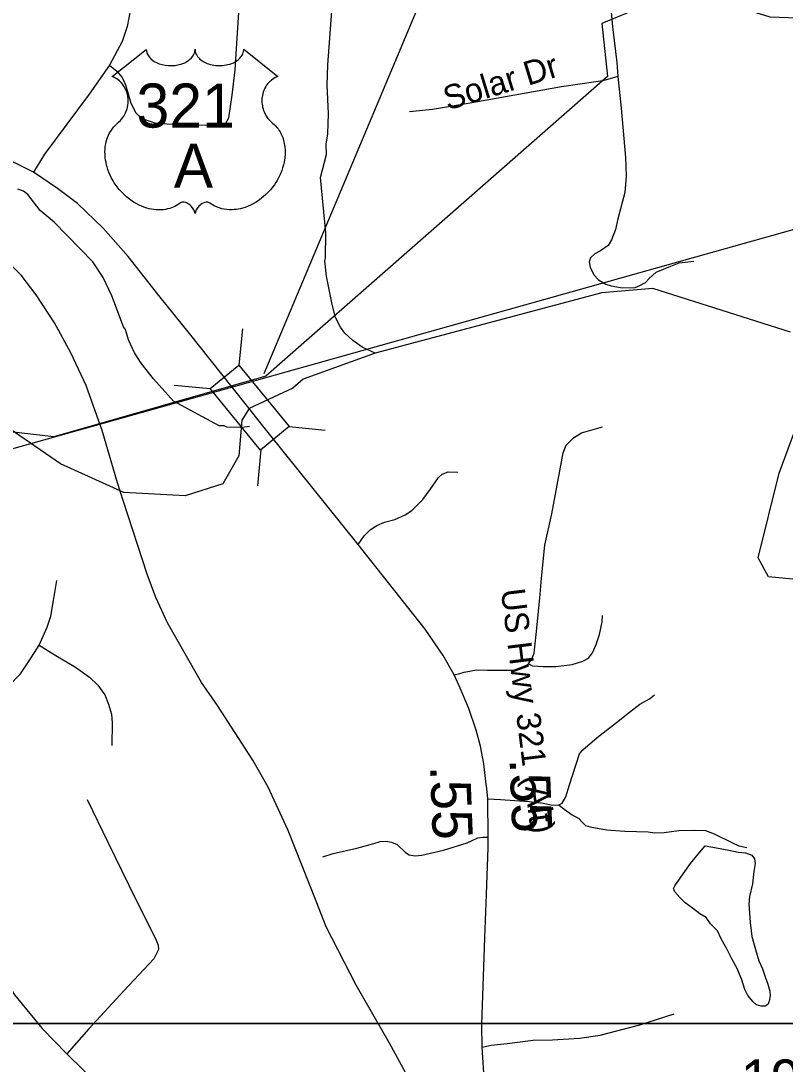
# Model space of a CAD drawing. Extents: x 1159738 to 1321356, y 736314 to 882035.
# Drawn here: x 1263980 to 1266364, y 766631 to 769885 of the extents above; entities that cross this region are included whole.
import ezdxf

# ---------------------------------------------------------------- set-up
doc = ezdxf.new("R2010")
doc.units = 0
for name, color, linetype in [('Exist Boundary Political City Limit New', 7, 'Continuous'), ('Exist Hydrographic Creek Single Shore', 7, 'Continuous'), ('Exist Hydrographic Misc Water Feature', 7, 'Continuous'), ('Exist Railroad Mainline', 7, 'Continuous'), ('Exist Road Non-System Type 51', 7, 'Continuous'), ('Exist Road Non-System Type 51 Label', 7, 'Continuous'), ('Exist Road Primary US Attributed', 7, 'Continuous'), ('Exist Road Primary US Label', 7, 'Continuous'), ('Exist Road Primary US Mileage Hundredths English Label', 7, 'Continuous'), ('Exist Road Primary US Shield CELL', 7, 'Continuous'), ('Exist Road Primary US Shield Number Label', 7, 'Continuous'), ('Exist Road Primary US Structure Standard Bridge CELL', 7, 'Continuous'), ('Exist Road Primary US Structure Standard Bridge Number Label', 7, 'Continuous'), ('Exist Road Secondary Mileage Hundredths English Label', 7, 'Continuous'), ('Exist Road Secondary Type 51 Number Label', 7, 'Continuous'), ('Map Preparation Boundary City Limit Buffer Line', 7, 'Continuous'), ('Map Preparation Inset Cut Line', 7, 'Continuous')]:
    doc.layers.add(name, color=color, linetype=linetype)

msp = doc.modelspace()

# ---------------------------------------------------------------- linework, layer by layer
at = {"layer": 'Exist Boundary Political City Limit New'}
for points in [[(1269986.4, 767284.9), (1268765.1, 767350.1), (1268594.9, 767532.3), (1268556.9, 767615.5), (1268556.9, 767674.9), (1268622, 767726), (1268786.7, 767711.3), (1268877.3, 767705.2), (1268933.1, 767837.1), (1268535.6, 768192.7), (1268644.9, 768487.5), (1268350.3, 768435.6), (1268332.7, 768458.1), (1268702.9, 769072.4), (1268291.5, 769323.6), (1267446.1, 769337.6), (1267449.1, 769737.8), (1267001.2, 769871.7), (1266318, 769896.5), (1266044.5, 769981.8), (1265792.3, 769877.3)], [(1265792.3, 769877.3), (1265809.7, 769711.8), (1264744.6, 768776.5), (1264082.9, 768587.5), (1263937.9, 768604.2), (1263679, 768704), (1263519.8, 768756.3), (1263427.7, 768754), (1263283.6, 768762.9), (1263035.1, 768711.1), (1262987.6, 768666), (1262932.9, 768525.7), (1262858.7, 768534.6), (1262700.3, 768541.9), (1262545.5, 768495), (1262098, 769128.8), (1262093.3, 768800.7), (1261203.3, 768836.2), (1261208, 768957.4), (1261046.5, 768957.4), (1261049.7, 769475.1), (1259666.9, 769484.6)], [(1260127.9, 766946.1), (1260871.4, 766933.2), (1261094.9, 766804.1), (1261119.5, 767044.5), (1261149.6, 767207.9), (1261209.7, 767384.2), (1261291.4, 767509), (1261424.1, 767761.8), (1261514.3, 767705.8), (1261634.7, 767718.7), (1261798, 767783.3), (1261991.4, 767925.2), (1262133.3, 768084.3), (1262546.9, 768155.9), (1267067, 769424.4), (1268424.7, 767365), (1269986.4, 767284.9)]]:
    msp.add_lwpolyline(points, dxfattribs=at)
at = {"layer": 'Exist Hydrographic Creek Single Shore'}
for points in [[(1266381.5, 768913.8), (1265951.5, 769050.5), (1265792.5, 769037.3), (1265085.8, 768848.9), (1264860.4, 768767.1), (1264828.4, 768739), (1264692.7, 768676.2)], [(1264692.7, 768676.2), (1264669.5, 768639.1), (1264660.4, 768528.3), (1264610.4, 768440.6), (1264492.4, 768403.6), (1264301.4, 768414), (1264103.4, 768503.3), (1263725.4, 768763.6), (1263543.4, 768826.3), (1263368.4, 768823.3), (1263125.4, 768746.2), (1263023.4, 768672.7), (1262854.5, 768242.8), (1262679.4, 768031.4), (1262372.4, 767970.2), (1262106.6, 768081.9), (1261784.4, 768477.6), (1261579.5, 768632.8), (1261488.4, 768660.8), (1261030.4, 768686.4), (1260890.4, 768741.7), (1260734.4, 768853.2)], [(1266453.4, 768137.7), (1266312.5, 768150.4), (1266280.5, 768210.1), (1266345.5, 768474.7), (1266443.5, 768738.6)]]:
    msp.add_lwpolyline(points, dxfattribs=at)
at = {"layer": 'Exist Hydrographic Misc Water Feature'}
for points in [[(1265085.8, 768848.9), (1265045.1, 768867.4), (1265015.7, 768888.3), (1264990.3, 768911), (1264976.9, 768929.4), (1264961.7, 768959.8), (1264950.8, 769000.1), (1264933.2, 769088.6), (1264928.6, 769136.7), (1264930.8, 769144.7), (1264931, 769224.6), (1264914.3, 769397.1), (1264933.8, 769468.5), (1264932.7, 769500.5), (1264937.5, 769532.4), (1264939.3, 769596.3), (1264935.7, 769684.4), (1264937.5, 769748.3), (1264950.2, 769915.9)], [(1264692.9, 768619.4), (1264670.1, 768616.3), (1264622.1, 768617.6), (1264614.2, 768621.8), (1264598.2, 768622.3), (1264456.3, 768698.4), (1264394.2, 768768.1), (1264355.6, 768817.2), (1264334.4, 768849.8), (1264315.6, 768890.4), (1264306.4, 768922.6), (1264300.7, 768930.8), (1264263.4, 769027.8), (1264236.9, 769084.5), (1264204.8, 769133.8), (1264083.7, 769256.9), (1264040.7, 769294.2), (1264002, 769343.2), (1263988.4, 769353.6), (1263970.6, 769360.1)], [(1266020.2, 767186.5), (1266046.1, 767223.8), (1266069.2, 767257), (1266092.9, 767285.8), (1266115, 767311.8), (1266150, 767305.1), (1266188.5, 767298.4), (1266217.8, 767291.9), (1266240.7, 767289.9), (1266260.6, 767283), (1266269, 767271.3), (1266270.7, 767256.1), (1266266.5, 767231.2), (1266262, 767192.6), (1266253.1, 767153.4), (1266251.2, 767129.7), (1266252.6, 767102.5), (1266254.7, 767072.3), (1266260.9, 767029.1), (1266272.1, 766988.7), (1266282.7, 766953.3), (1266293.5, 766927.9), (1266301.6, 766903.3), (1266310.3, 766880.1), (1266317, 766858.5), (1266317.3, 766843.4), (1266314, 766827), (1266310.2, 766816.4), (1266302.2, 766811.5), (1266290, 766811.8), (1266275, 766815.1), (1266264.5, 766825.4), (1266247.8, 766844.5), (1266238.9, 766863.3), (1266228.9, 766893.7), (1266214.7, 766929.2), (1266198.2, 766959), (1266183.1, 766988.1), (1266165.2, 767021.5), (1266152.9, 767046.2), (1266131.3, 767068.3), (1266118.2, 767088), (1266098.3, 767099.2), (1266075.8, 767117), (1266052.6, 767134.1), (1266036.4, 767148.9), (1266020.4, 767168.6), (1266015.7, 767178.7), (1266020.2, 767186.5)]]:
    msp.add_lwpolyline(points, dxfattribs=at)
at = {"layer": 'Exist Railroad Mainline'}
for points in [[(1264281.3, 768444.1), (1264233.5, 768607.8), (1264183.6, 768747.6), (1264136.4, 768849.8), (1264085.4, 768942.9), (1264028.3, 769030.3), (1263981, 769091.8), (1263927.3, 769146.5), (1263875.7, 769189.9), (1263816.4, 769230.6), (1263736.9, 769273.8), (1263650.2, 769312.2), (1263545.8, 769354), (1263471.5, 769380.8), (1263402.3, 769405.5), (1263335.3, 769424.2), (1263249, 769444), (1263167.5, 769457), (1263075.7, 769468.5), (1263015.5, 769476.9)], [(1265522.8, 765944.2), (1265401.8, 766180.2), (1265353.4, 766273.7), (1265211.8, 766545.2), (1265130.2, 766695.9), (1265026.4, 766877.3), (1264932.6, 767059.2), (1264900.8, 767138.9), (1264813.5, 767359.9), (1264751.5, 767494.9), (1264703.2, 767579), (1264593.4, 767749), (1264544, 767821), (1264437.1, 768007.3), (1264400.9, 768086.5), (1264374.5, 768159), (1264299.9, 768385.6), (1264281.3, 768444.1)]]:
    msp.add_lwpolyline(points, dxfattribs=at)
at = {"layer": 'Exist Road Non-System Type 51'}
for points in [[(1266066, 770870.2), (1266030.6, 770807.6), (1265948.3, 770665.5), (1265942.1, 770652.5), (1265918.2, 770591.5), (1265896.9, 770544.9), (1265847.6, 770463.9), (1265831.8, 770434.7), (1265818.1, 770399.7), (1265807.8, 770366.1), (1265798.9, 770317.4), (1265794.1, 770271.4), (1265790.1, 770205.1), (1265793.5, 770140), (1265800.3, 770069.1), (1265817.5, 769957.9), (1265825.5, 769867.2), (1265839.4, 769755.3), (1265842.1, 769712)], [(1264356.4, 770405.7), (1264340.8, 770174.4), (1264325.3, 769971.9), (1264322.5, 769922), (1264311.7, 769867.8), (1264295.6, 769821.1), (1264256.8, 769746.9), (1264193.6, 769657), (1264053.8, 769469.2), (1264019, 769413.7)], [(1264256.8, 769746.9), (1264279.2, 769728.6), (1264296, 769708.2), (1264306.2, 769685.5), (1264323, 769628.6), (1264339, 769598.7), (1264357.9, 769581.2), (1264404.6, 769565.2), (1264593.4, 769559.4), (1264619.6, 769565.9), (1264628.4, 769582.7), (1264639.3, 769653.4), (1264648.8, 769732.2), (1264654.6, 769831.4), (1264663.4, 769961.4)], [(1265842.1, 769712), (1265795.2, 769698.7), (1265666.4, 769679.5), (1265375.5, 769627.4), (1265263.7, 769608.7), (1265192.5, 769601.8)], [(1265842.1, 769712), (1265853.2, 769613.3), (1265866, 769459.3), (1265868.1, 769401.2), (1265863.8, 769349.5), (1265842, 769268.2), (1265834.6, 769234.7), (1265822.9, 769202.7), (1265812.7, 769185), (1265788.8, 769167.4), (1265770.7, 769158.4), (1265756.8, 769146.1), (1265752.6, 769133.3), (1265755.8, 769116.8), (1265768, 769093.4), (1265782.4, 769077.9), (1265805.3, 769064.1), (1265821.8, 769058.7), (1265856.9, 769052.3), (1265896.8, 769053.9), (1265911.2, 769059.3), (1265928.8, 769069.4), (1265940.5, 769081.6), (1265961.8, 769101.4), (1266008.1, 769120.5), (1266033.6, 769130.7), (1266079.4, 769135.5)], [(1265563.2, 767879.9), (1265574.5, 767894.8), (1265580.9, 767912.5), (1265587.2, 767971.3), (1265598.6, 768084.6), (1265604.2, 768146.2), (1265614.8, 768249.9), (1265636, 768346.9), (1265661.4, 768481.1), (1265672, 768537.7), (1265681.2, 768561.1), (1265703.9, 768584.5), (1265729.3, 768600.1), (1265794.4, 768619.2)], [(1265032.2, 768251.7), (1265051.3, 768278.6), (1265069.7, 768297.7), (1265091, 768311.2), (1265114.3, 768321.8), (1265146.2, 768329.6), (1265179.4, 768344.5), (1265199.9, 768357.9), (1265233.9, 768391.9), (1265256.6, 768423.1), (1265282.7, 768460.6), (1265294.6, 768471.1), (1265313, 768478.2), (1265343.4, 768477.5)], [(1264037.5, 767937.8), (1264061.7, 767993.7), (1264073.5, 768028.3), (1264082.2, 768076.6), (1264092.5, 768139.2)], [(1265563.2, 767879.9), (1265576.3, 767872.8), (1265609.6, 767870.6), (1265648.5, 767871.3), (1265699.5, 767877.7), (1265732.7, 767887.6), (1265751.1, 767896.8), (1265763.2, 767913.8), (1265774.5, 767939.3), (1265785.1, 767971.2), (1265793.6, 768010.1), (1265795, 768030)], [(1263912.4, 767779.5), (1263935.2, 767803.1), (1263978.6, 767848.7), (1264005.8, 767888.4), (1264037.5, 767937.8)], [(1264037.5, 767937.8), (1264084.4, 767908.3), (1264150.6, 767868.6), (1264193.9, 767837.7), (1264220.4, 767812.7), (1264241.8, 767782.5), (1264253.5, 767753.8), (1264262.3, 767722.9), (1264264.5, 767695.6), (1264263.8, 767625.1)], [(1265332, 767845.3), (1265349.7, 767849.6), (1265362.9, 767853), (1265401.8, 767860.8), (1265435.8, 767860.1), (1265520, 767860.1), (1265540.5, 767865), (1265557.5, 767875), (1265563.2, 767879.9)], [(1265657.8, 767439.5), (1265668.4, 767444.5), (1265680.4, 767464.3), (1265691.1, 767501.9), (1265722.9, 767598.9), (1265733.5, 767611.6), (1265778.1, 767649.9), (1265838, 767696), (1265878.4, 767728.6), (1265910.9, 767753.4), (1265941.3, 767769.7), (1265956.9, 767783.2)], [(1264187.2, 767456.2), (1264252.1, 767320.8), (1264337.6, 767146.4), (1264400.4, 767023), (1264408, 767001.3), (1264409.1, 766988.3), (1264404.7, 766977.5), (1264395, 766959.1), (1264300.9, 766859.1), (1264191.6, 766741), (1264123.1, 766662.3)], [(1265437, 767457.9), (1265475.9, 767455.8), (1265565.8, 767450.2), (1265609, 767444.5), (1265634.4, 767439.5), (1265648.6, 767438.1), (1265657.8, 767439.5)], [(1265657.8, 767439.5), (1265674.8, 767425.6), (1265700.2, 767408.6), (1265720.8, 767396.6), (1265730.7, 767385.2), (1265741.1, 767375.4), (1265756, 767370.5), (1265806.9, 767362), (1265864.3, 767357.7), (1265937.2, 767355.6), (1265957, 767352), (1265986.7, 767353.5), (1266032.7, 767359.1), (1266082.2, 767360.5), (1266116.2, 767359.1), (1266142.4, 767349.2), (1266200.4, 767320.9), (1266220, 767311.7), (1266244.8, 767306.1)], [(1264922.3, 767276.8), (1264954.1, 767288.1), (1265027.7, 767304.4), (1265081.5, 767319.3), (1265101.3, 767325), (1265118.3, 767325.7), (1265136, 767323.5), (1265154.4, 767315.7), (1265179.9, 767290.3), (1265191.2, 767283.2), (1265210.3, 767280.3), (1265230.8, 767282.5), (1265298.8, 767298), (1265372.4, 767321.4), (1265405.6, 767337), (1265421.2, 767339.1), (1265438.2, 767339.1)], [(1263918.2, 766911.8), (1263960.2, 766847.2), (1264046.1, 766741.8), (1264123.1, 766662.3)], [(1265418.9, 766683), (1265447.2, 766690), (1265497.4, 766695), (1265578.1, 766704.9), (1265638.9, 766706.3), (1265723.2, 766712), (1265786.9, 766720.5), (1265911, 766753), (1265989.5, 766778.5), (1266018.4, 766787.9)], [(1264123.1, 766662.3), (1264282, 766507.8), (1264434.9, 766363.3), (1264579.5, 766228.5), (1264692.8, 766118.8), (1264845.4, 765980.1), (1264897.2, 765926.5), (1264922.8, 765887.5), (1264941.6, 765846.3), (1264960.4, 765784.4)]]:
    msp.add_lwpolyline(points, dxfattribs=at)
at = {"layer": 'Exist Road Primary US Attributed'}
for points in [[(1264638.8, 768742.9), (1264506.2, 768909.8), (1264414.9, 769023.8), (1264314.5, 769150.6), (1264236.8, 769238.1), (1264156.8, 769315.3), (1264094.5, 769362.7), (1264019, 769413.7), (1263903.1, 769470.6)], [(1264692.7, 768676.2), (1264638.8, 768742.9)], [(1265426.4, 766571.3), (1265418.9, 766683), (1265418.5, 766754), (1265427.4, 767025), (1265432.2, 767159.4), (1265437.6, 767306.2), (1265438.2, 767339.1), (1265437, 767457.9), (1265433.6, 767490.6), (1265432.1, 767503.6), (1265424.2, 767567.1), (1265413.8, 767622.3), (1265400.5, 767672.7), (1265377.8, 767739.7), (1265347.8, 767811.2), (1265332, 767845.3), (1265297.1, 767905.1), (1265241.5, 767987.7), (1265032.2, 768251.7), (1264755.7, 768595.5), (1264735.2, 768621.7), (1264692.7, 768676.2)]]:
    msp.add_lwpolyline(points, dxfattribs=at)
at = {"layer": 'Exist Road Primary US Shield CELL'}
msp.add_lwpolyline([(1264371.3, 769796.5), (1264371.6, 769792.1), (1264372.7, 769786.9), (1264373.5, 769784.2), (1264375.9, 769779), (1264380, 769773), (1264385.6, 769767), (1264391.9, 769761.8), (1264396.2, 769759), (1264403.4, 769755.1), (1264411.7, 769751.7), (1264420.8, 769749), (1264430.2, 769747.1), (1264440.4, 769746), (1264450.5, 769745.8), (1264461.4, 769746.6), (1264473.5, 769749), (1264479.1, 769750.4), (1264485.3, 769752.5), (1264491.1, 769754.9), (1264497.4, 769758.3), (1264502.5, 769761.6), (1264506.5, 769764.5), (1264512.1, 769769.9), (1264516.6, 769775.5), (1264518.5, 769778.6), (1264520.1, 769781.6), (1264522.4, 769788), (1264523, 769790.9), (1264523.4, 769796.7), (1264523.8, 769791.8), (1264524.3, 769788.7), (1264525.1, 769785.7), (1264526.4, 769782.5), (1264528.6, 769778), (1264531.1, 769774.2), (1264535.9, 769768.6), (1264538.8, 769765.9), (1264541.5, 769763.7), (1264548.7, 769758.7), (1264557.2, 769754.4), (1264561.3, 769752.6), (1264565.6, 769751.1), (1264571, 769749.5), (1264576.6, 769748.1), (1264582.1, 769747.2), (1264587.8, 769746.4), (1264593.5, 769746), (1264598.2, 769745.8), (1264604, 769745.9), (1264609.3, 769746.2), (1264614.8, 769746.8), (1264620.8, 769747.8), (1264625.7, 769748.9), (1264632.1, 769750.6), (1264637.8, 769752.7), (1264642.9, 769754.9), (1264649.5, 769758.3), (1264654.9, 769761.7), (1264658.7, 769764.8), (1264663.4, 769769.1), (1264667.8, 769774.1), (1264670.4, 769777.9), (1264672.2, 769781.7), (1264673.9, 769785.7), (1264674.9, 769790), (1264675.4, 769793.7), (1264675.5, 769796.8), (1264781.8, 769712.2), (1264779.3, 769711.2), (1264773.5, 769708.4), (1264768.9, 769705.7), (1264761.6, 769700.5), (1264758.5, 769697.7), (1264755.3, 769694.8), (1264752.5, 769691.6), (1264749.9, 769688.7), (1264746.8, 769684.4), (1264744.1, 769680.1), (1264741.4, 769675.4), (1264739.4, 769671.3), (1264736.1, 769662.8), (1264734.6, 769657.4), (1264733.6, 769652.8), (1264732.3, 769643.3), (1264732, 769638.8), (1264732, 769634.4), (1264732.2, 769629.6), (1264732.7, 769625.1), (1264733.5, 769620.4), (1264734.3, 769616.3), (1264735.6, 769611.2), (1264737.5, 769605.3), (1264739.8, 769599.6), (1264744.6, 769590.3), (1264750.9, 769580.9), (1264755.3, 769575.6), (1264759.7, 769571.1), (1264766.3, 769565.6), (1264769.8, 769562.5), (1264773.9, 769558.4), (1264780.6, 769550.6), (1264783.3, 769547), (1264786, 769542.9), (1264788.5, 769538.7), (1264791, 769534.2), (1264793, 769530.2), (1264796.8, 769521.1), (1264799.5, 769512.3), (1264800.8, 769507.6), (1264802.7, 769497.2), (1264803.5, 769492.1), (1264804.3, 769481.9), (1264804.3, 769469.6), (1264803.4, 769457.9), (1264801.2, 769444.3), (1264799.4, 769436.1), (1264796.6, 769426.6), (1264793.9, 769418.4), (1264789, 769406.3), (1264784.7, 769397.5), (1264779.1, 769387.2), (1264775.3, 769381), (1264770.8, 769374.3), (1264765.3, 769366.6), (1264758.7, 769358.5), (1264750.9, 769349.9), (1264744.5, 769343.5), (1264736.3, 769336.1), (1264731.2, 769332), (1264724.1, 769326.6), (1264714.3, 769320), (1264704.6, 769314.5), (1264696.4, 769310.2), (1264689.1, 769307.1), (1264679.7, 769303.5), (1264664, 769299.2), (1264658.3, 769298), (1264651.5, 769297), (1264645.2, 769296.4), (1264639, 769296), (1264630.8, 769296), (1264622.5, 769296.6), (1264614.7, 769297.8), (1264606.7, 769299.4), (1264598.2, 769302), (1264590.5, 769305), (1264582.7, 769308.8), (1264569.6, 769317.1), (1264565.8, 769319.1), (1264563.6, 769319.7), (1264558.5, 769319.9), (1264553.8, 769318.9), (1264548.9, 769317), (1264545.9, 769315.4), (1264542, 769312.8), (1264539, 769310.4), (1264535.3, 769307), (1264532.8, 769304.1), (1264530.9, 769301.8), (1264527.2, 769296), (1264525.9, 769293.2), (1264524.5, 769289.7), (1264523.3, 769284.4), (1264521.6, 769291), (1264519.7, 769295.4), (1264517.4, 769299.2), (1264515.1, 769302.5), (1264511.4, 769306.8), (1264508, 769310), (1264504, 769313.3), (1264499.8, 769315.8), (1264496.3, 769317.6), (1264493.2, 769318.8), (1264489.4, 769319.7), (1264486.2, 769320), (1264483.7, 769319.9), (1264480.1, 769319.1), (1264475.3, 769315.7), (1264470.8, 769312.5), (1264465.8, 769309.4), (1264459.9, 769306.3), (1264455.6, 769304.3), (1264450.4, 769302.3), (1264444.4, 769300.3), (1264437.9, 769298.6), (1264431.2, 769297.2), (1264425.3, 769296.3), (1264418.9, 769295.7), (1264413.2, 769295.6), (1264407.2, 769295.6), (1264401.7, 769296.1), (1264395.2, 769296.6), (1264387.2, 769297.8), (1264380.5, 769299.3), (1264373.5, 769301.2), (1264366.3, 769303.5), (1264358.5, 769306.4), (1264348.9, 769310.6), (1264342.2, 769314.1), (1264331.5, 769320.2), (1264319.1, 769328.8), (1264309.7, 769336.4), (1264302.9, 769342.6), (1264292.8, 769352.9), (1264286.8, 769359.6), (1264277.5, 769371.7), (1264271.5, 769380.4), (1264267.7, 769386.8), (1264262, 769397.1), (1264258.9, 769403.6), (1264254.9, 769413), (1264251.7, 769421.6), (1264249.1, 769429.8), (1264247.7, 769435), (1264245.7, 769444.1), (1264244.5, 769450.5), (1264243.3, 769459.4), (1264242.6, 769468.8), (1264242.5, 769477.4), (1264242.7, 769484.5), (1264243.5, 769492.9), (1264244.9, 769501.7), (1264246.6, 769509.3), (1264248.2, 769514.8), (1264250.4, 769521.4), (1264253.4, 769528.8), (1264256.9, 769535.8), (1264260.3, 769541.7), (1264264.5, 769547.9), (1264268.6, 769553.3), (1264274.1, 769559.2), (1264279.7, 769564.6), (1264284.9, 769568.8), (1264291, 769574.8), (1264294.2, 769578.5), (1264298.1, 769583.5), (1264301.2, 769588.3), (1264303.6, 769592.5), (1264306.9, 769598.7), (1264308.8, 769603.3), (1264311.2, 769610.5), (1264312.5, 769615.5), (1264313.7, 769622), (1264314.5, 769628.1), (1264314.9, 769635.7), (1264314.7, 769642), (1264313.9, 769649.3), (1264312.5, 769656.3), (1264310.8, 769662.5), (1264308.2, 769669.5), (1264305.8, 769674.7), (1264301.7, 769681.6), (1264297.2, 769688.1), (1264292.5, 769693.4), (1264287.8, 769698.1), (1264283.3, 769701.6), (1264279, 769704.7), (1264273.6, 769708), (1264268.3, 769710.5), (1264265.1, 769711.8)], close=True, dxfattribs=at)
at = {"layer": 'Exist Road Primary US Structure Standard Bridge CELL'}
for p, q in [((1264671.2, 768924.1), (1264660, 768811.5)), ((1264457.8, 768749.3), (1264570.4, 768738.1)), ((1264816.6, 768619.4), (1264929.3, 768608.2)), ((1264729.1, 768547.6), (1264717.9, 768435))]:
    msp.add_line(p, q, dxfattribs=at)
msp.add_lwpolyline([(1264660, 768811.5), (1264817.1, 768619.7), (1264727.5, 768546.3), (1264570.4, 768738.1)], close=True, dxfattribs=at)
at = {"layer": 'Exist Road Primary US Structure Standard Bridge Number Label'}
msp.add_line((1264738.9, 768785.3), (1265330.7, 770194.3), dxfattribs=at)
at = {"layer": 'Map Preparation Boundary City Limit Buffer Line'}
for points in [[(1269986.4, 767284.9), (1268765.1, 767350.1), (1268594.9, 767532.3), (1268556.9, 767615.5), (1268556.9, 767674.9), (1268622, 767726), (1268786.7, 767711.3), (1268877.3, 767705.2), (1268933.1, 767837.1), (1268535.6, 768192.7), (1268644.9, 768487.5), (1268350.3, 768435.6), (1268332.7, 768458.1), (1268702.9, 769072.4), (1268291.5, 769323.6), (1267446.1, 769337.6), (1267449.1, 769737.8), (1267001.2, 769871.7), (1266318, 769896.5), (1266044.5, 769981.8), (1265792.3, 769877.3)], [(1265792.3, 769877.3), (1265809.7, 769711.8), (1264744.6, 768776.5), (1264082.9, 768587.5), (1263937.9, 768604.2), (1263679, 768704), (1263519.8, 768756.3), (1263427.7, 768754), (1263283.6, 768762.9), (1263035.1, 768711.1), (1262987.6, 768666), (1262932.9, 768525.7), (1262858.7, 768534.6), (1262700.3, 768541.9), (1262545.5, 768495), (1262098, 769128.8), (1262093.3, 768800.7), (1261203.3, 768836.2), (1261208, 768957.4), (1261046.5, 768957.4), (1261049.7, 769475.1), (1259666.9, 769484.6)], [(1260127.9, 766946.1), (1260871.4, 766933.2), (1261094.9, 766804.1), (1261119.5, 767044.5), (1261149.6, 767207.9), (1261209.7, 767384.2), (1261291.4, 767509), (1261424.1, 767761.8), (1261514.3, 767705.8), (1261634.7, 767718.7), (1261798, 767783.3), (1261991.4, 767925.2), (1262133.3, 768084.3), (1262546.9, 768155.9), (1267067, 769424.4), (1268424.7, 767365), (1269986.4, 767284.9)]]:
    msp.add_lwpolyline(points, dxfattribs=at)
at = {"layer": 'Map Preparation Inset Cut Line'}
for points in [[(1213574.8, 811005.5), (1289258, 811005.5), (1289258, 782300.2), (1274049.2, 782296.9), (1274049.2, 766757), (1213574.8, 766757)], [(1232800.5, 766757), (1308483.8, 766757), (1308483.8, 738579.5), (1232800.5, 738579.5)]]:
    msp.add_lwpolyline(points, close=True, dxfattribs=at)

# ---------------------------------------------------------------- texts
at = {"layer": 'Exist Road Non-System Type 51 Label'}
msp.add_text('Solar Dr', height=75, rotation=17.1121, dxfattribs=at).set_placement((1265311.6, 769605.5))
at = {"layer": 'Exist Road Primary US Label'}
msp.add_text('US Hwy 321 (Alt)', height=75, rotation=277.0315, dxfattribs=at).set_placement((1265477.3, 768110))
at = {"layer": 'Exist Road Primary US Mileage Hundredths English Label'}
msp.add_text('.55', height=125, rotation=272.1895, dxfattribs=at).set_placement((1265504.5, 767582.9))
at = {"layer": 'Exist Road Primary US Shield Number Label'}
for s, p in [('321', (1264340.7, 769552.4)), ('A', (1264457.1, 769364.5))]:
    msp.add_text(s, height=137.5, dxfattribs=at).set_placement(p)
at = {"layer": 'Exist Road Secondary Mileage Hundredths English Label'}
msp.add_text('.55', height=125, rotation=272.1895, dxfattribs=at).set_placement((1265256.6, 767561))
at = {"layer": 'Exist Road Secondary Type 51 Number Label'}
msp.add_text('1965', height=125, dxfattribs=at).set_placement((1266226.2, 766520.1))

doc.saveas('drawing.dxf')
